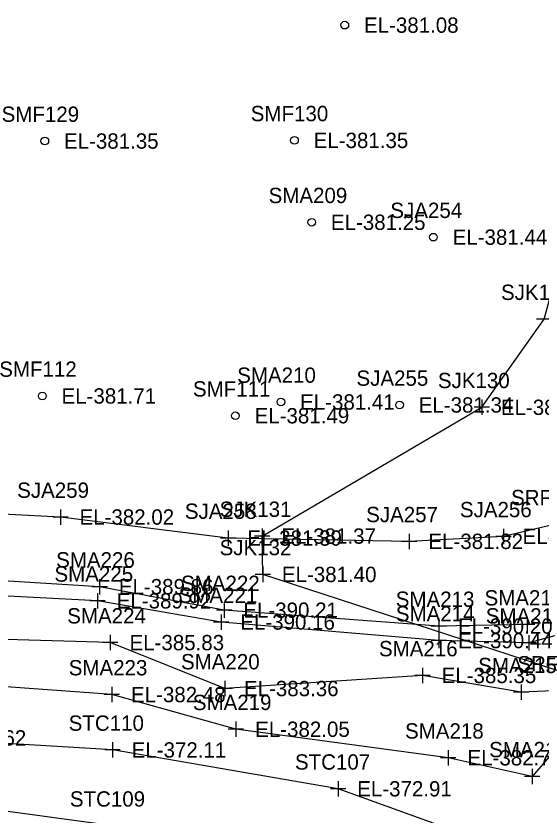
# Model space of a CAD drawing. Extents: x 1189978 to 1314812, y 571533 to 629339.
# Drawn here: x 1217385.9 to 1217522.9, y 621752.1 to 621960.6 of the extents above; entities that cross this region are included whole.
import ezdxf

# ---------------------------------------------------------------- set-up
doc = ezdxf.new("R2010")
doc.units = 0
for name, color, linetype in [('SURVEY - DRAINAGE - Bridge Hydraulic Data - Points - Elevations', 7, 'Continuous'), ('SURVEY - DRAINAGE - Bridge Hydraulic Data - Points - Numbers', 7, 'Continuous'), ('SURVEY - DRAINAGE - Bridge Hydraulic Data with Text', 7, 'Continuous'), ('SURVEY - DRAINAGE - Natural Features', 7, 'Continuous'), ('SURVEY - DRAINAGE - Natural Features - Points - Numbers', 7, 'Continuous'), ('SURVEY - DTM - Breaklines', 7, 'Continuous'), ('SURVEY - DTM - Breaklines - Points - Elevations', 7, 'Continuous'), ('SURVEY - DTM - Breaklines - Points - Locators', 7, 'Continuous'), ('SURVEY - DTM - Breaklines - Points - Numbers', 7, 'Continuous'), ('SURVEY - DTM - Spot Points - Elevations', 7, 'Continuous'), ('SURVEY - DTM - Spot Points - Locators', 7, 'Continuous'), ('SURVEY - DTM - Spot Points - Point Numbers', 7, 'Continuous'), ('SURVEY - VEGETATION - Features - Points - Elevations', 7, 'Continuous'), ('SURVEY - VEGETATION - Features - Points - Locators', 7, 'Continuous'), ('SURVEY - VEGETATION - Features - Points - Numbers', 7, 'Continuous'), ('SURVEY - VEGETATION - Features with Text', 7, 'Continuous')]:
    doc.layers.add(name, color=color, linetype=linetype)

msp = doc.modelspace()

# ---------------------------------------------------------------- linework, layer by layer
at = {"layer": 'SURVEY - DRAINAGE - Bridge Hydraulic Data with Text'}
for p, q in [((1217410.9, 621785.5), (1217410.9, 621781.5)), ((1217412.9, 621783.5), (1217408.9, 621783.5)), ((1217443.29, 621776.44), (1217443.29, 621772.44)), ((1217445.29, 621774.44), (1217441.29, 621774.44)), ((1217411.07, 621771.04), (1217411.07, 621767.04)), ((1217413.07, 621769.04), (1217409.07, 621769.04)), ((1217498.68, 621769), (1217498.68, 621765)), ((1217500.68, 621767), (1217496.68, 621767)), ((1217520.57, 621764.14), (1217520.57, 621760.14)), ((1217522.57, 621762.14), (1217518.57, 621762.14)), ((1217469.91, 621760.9), (1217469.91, 621756.9)), ((1217471.91, 621758.9), (1217467.91, 621758.9))]:
    msp.add_line(p, q, dxfattribs=at)
for points in [[(1217517.89, 621741.61), (1217469.91, 621758.9), (1217411.07, 621769.04), (1217358.89, 621772.19), (1217311.12, 621779.99), (1217259.84, 621789.4), (1217219.68, 621791.7), (1217168.44, 621804.62), (1217102.61, 621815.67), (1217052.63, 621809.41), (1217001.8, 621792.08), (1216983.34, 621768.8), (1216930.91, 621758.26)], [(1217410.9, 621783.5), (1217348.6, 621788.05), (1217293.38, 621789.05)], [(1217537.02, 621781.08), (1217520.57, 621762.14), (1217498.68, 621767), (1217443.29, 621774.44), (1217410.9, 621783.5)]]:
    msp.add_lwpolyline(points, dxfattribs=at)
at = {"layer": 'SURVEY - DRAINAGE - Natural Features'}
msp.add_lwpolyline([(1217597.92, 621711.33), (1217564.54, 621718.36), (1217512.62, 621725.38), (1217463.25, 621735.87), (1217411.22, 621749.25), (1217354.3, 621757.02), (1217307.69, 621764.42), (1217256.95, 621775.42), (1217216.84, 621778.16), (1217165.85, 621785.07), (1217102.13, 621795.43), (1217054.86, 621791.1), (1217006.99, 621774.19), (1216986.41, 621760.64), (1216952.38, 621744.49)], dxfattribs=at)
at = {"layer": 'SURVEY - DTM - Breaklines'}
for points in [[(1217685.05, 622529.18), (1217678.55, 622499.44), (1217670.66, 622464.16), (1217662, 622418.29), (1217653.65, 622375.31), (1217647.46, 622326.5), (1217637.7, 622278.06), (1217624.97, 622233.51), (1217617.77, 622187.81), (1217609.29, 622147.05), (1217599.66, 622101.36), (1217592.56, 622056.45), (1217583.44, 622007.19), (1217575.28, 621964.22), (1217564.77, 621919.14), (1217554.54, 621865.01), (1217546.46, 621821.67), (1217537.02, 621781.08), (1217528.09, 621784.53), (1217517.71, 621784.08)], [(1217526.29, 621827.9), (1217513.05, 621824.77), (1217488.49, 621823.48), (1217441.24, 621824.34), (1217397.47, 621829.83), (1217345.53, 621832.46), (1217295.63, 621831.2), (1217245.72, 621829.59), (1217196.06, 621848.65), (1217142.73, 621858.18), (1217088.87, 621861), (1217031.95, 621852.21), (1216981.96, 621833.21)], [(1217519.22, 621801.74), (1217496.21, 621801.38), (1217440.2, 621805.52), (1217407.73, 621811.65), (1217355.92, 621814.85), (1217296.27, 621811.58)], [(1217534.84, 621801.11), (1217519.7, 621797.03), (1217496.23, 621797.58), (1217439.41, 621802.43), (1217407.18, 621807.95), (1217355.45, 621810.65), (1217295.81, 621806.41)], [(1217517.71, 621784.08), (1217491.94, 621788.48), (1217440.37, 621785.07), (1217410.51, 621797.05), (1217352.9, 621798.74)]]:
    msp.add_lwpolyline(points, dxfattribs=at)
at = {"layer": 'SURVEY - DTM - Breaklines - Points - Locators'}
for p, q in [((1217397.47, 621831.83), (1217397.47, 621827.83)), ((1217399.47, 621829.83), (1217395.47, 621829.83)), ((1217441.24, 621826.34), (1217441.24, 621822.34)), ((1217513.05, 621826.77), (1217513.05, 621822.77)), ((1217443.24, 621824.34), (1217439.24, 621824.34)), ((1217488.49, 621825.48), (1217488.49, 621821.48)), ((1217515.05, 621824.77), (1217511.05, 621824.77)), ((1217490.49, 621823.48), (1217486.49, 621823.48)), ((1217407.73, 621813.65), (1217407.73, 621809.65)), ((1217409.73, 621811.65), (1217405.73, 621811.65)), ((1217407.18, 621809.95), (1217407.18, 621805.95)), ((1217409.18, 621807.95), (1217405.18, 621807.95)), ((1217440.2, 621807.52), (1217440.2, 621803.52)), ((1217442.2, 621805.52), (1217438.2, 621805.52)), ((1217439.41, 621804.43), (1217439.41, 621800.43)), ((1217496.21, 621803.38), (1217496.21, 621799.38)), ((1217519.22, 621803.74), (1217519.22, 621799.74)), ((1217441.41, 621802.43), (1217437.41, 621802.43)), ((1217498.21, 621801.38), (1217494.21, 621801.38)), ((1217521.22, 621801.74), (1217517.22, 621801.74)), ((1217410.51, 621799.05), (1217410.51, 621795.05)), ((1217496.23, 621799.58), (1217496.23, 621795.58)), ((1217519.7, 621799.03), (1217519.7, 621795.03)), ((1217412.51, 621797.05), (1217408.51, 621797.05)), ((1217498.23, 621797.58), (1217494.23, 621797.58)), ((1217521.7, 621797.03), (1217517.7, 621797.03)), ((1217491.94, 621790.48), (1217491.94, 621786.48)), ((1217493.94, 621788.48), (1217489.94, 621788.48)), ((1217440.37, 621787.07), (1217440.37, 621783.07)), ((1217442.37, 621785.07), (1217438.37, 621785.07)), ((1217519.71, 621784.08), (1217515.71, 621784.08)), ((1217517.71, 621786.08), (1217517.71, 621782.08))]:
    msp.add_line(p, q, dxfattribs=at)
at = {"layer": 'SURVEY - DTM - Spot Points - Locators'}
for centre in [(1217471.68, 621958.19), (1217393.42, 621927.95), (1217458.55, 621928.12), (1217463.05, 621906.75), (1217494.8, 621902.86), (1217392.77, 621861.42), (1217455.02, 621859.85), (1217485.96, 621859.07), (1217443.14, 621856.26)]:
    msp.add_circle(centre, 1, dxfattribs=at)
at = {"layer": 'SURVEY - VEGETATION - Features - Points - Locators'}
for p, q in [((1217525.69, 621881.47), (1217521.69, 621881.47)), ((1217507.38, 621860.46), (1217507.38, 621856.46)), ((1217509.38, 621858.46), (1217505.38, 621858.46)), ((1217450.11, 621826.86), (1217450.11, 621822.86)), ((1217452.11, 621824.86), (1217448.11, 621824.86)), ((1217450.26, 621816.85), (1217450.26, 621812.85)), ((1217450.26, 621816.85), (1217450.26, 621812.85)), ((1217452.26, 621814.85), (1217448.26, 621814.85)), ((1217452.26, 621814.85), (1217448.26, 621814.85))]:
    msp.add_line(p, q, dxfattribs=at)
at = {"layer": 'SURVEY - VEGETATION - Features with Text'}
msp.add_lwpolyline([(1217575.08, 621774.11), (1217450.26, 621814.85), (1217450.11, 621824.86), (1217507.38, 621858.46), (1217523.69, 621881.47), (1217539.67, 621940.19), (1217555.11, 622005.06), (1217569.39, 622072.91), (1217588.39, 622140.3), (1217598.23, 622184.22), (1217608.56, 622234.27), (1217619.43, 622285.83), (1217630.65, 622335.58), (1217641.81, 622391.46), (1217652.67, 622449.04), (1217659.71, 622500.99), (1217665.15, 622519.94)], dxfattribs=at)

# ---------------------------------------------------------------- texts
at = {"layer": 'SURVEY - DRAINAGE - Bridge Hydraulic Data - Points - Elevations'}
for s, p in [('EL-382.48', (1217415.9, 621781.5)), ('EL-382.05', (1217448.29, 621772.44)), ('EL-372.62', (1217363.89, 621770.19)), ('EL-372.11', (1217416.07, 621767.04)), ('EL-382.74', (1217503.68, 621765)), ('EL-372.91', (1217474.91, 621756.9))]:
    msp.add_text(s, height=4, dxfattribs=at).set_placement(p)
at = {"layer": 'SURVEY - DRAINAGE - Bridge Hydraulic Data - Points - Numbers'}
for s, p in [('SMA223', (1217399.66, 621788.5)), ('SMA219', (1217432.03, 621779.44)), ('STC110', (1217399.65, 621774.04)), ('SMA218', (1217487.39, 621772)), ('SMA217', (1217509.33, 621767.14)), ('STC107', (1217458.67, 621763.9))]:
    msp.add_text(s, height=4, dxfattribs=at).set_placement(p)
at = {"layer": 'SURVEY - DRAINAGE - Natural Features - Points - Numbers'}
msp.add_text('STC109', height=4, dxfattribs=at).set_placement((1217399.96, 621754.25))
at = {"layer": 'SURVEY - DTM - Breaklines - Points - Elevations'}
for s, p in [('EL-382.02', (1217402.47, 621827.83)), ('EL-381.39', (1217446.24, 621822.34)), ('EL-382.25', (1217518.05, 621822.77)), ('EL-381.82', (1217493.49, 621821.48)), ('EL-389.86', (1217412.73, 621809.65)), ('EL-389.92', (1217412.18, 621805.95)), ('EL-390.21', (1217445.2, 621803.52)), ('EL-390.16', (1217444.41, 621800.43)), ('EL-390.20', (1217501.21, 621799.38)), ('EL-385.83', (1217415.51, 621795.05)), ('EL-390.44', (1217501.23, 621795.58)), ('EL-385.35', (1217496.94, 621786.48)), ('EL-383.36', (1217445.37, 621783.07))]:
    msp.add_text(s, height=4, dxfattribs=at).set_placement(p)
at = {"layer": 'SURVEY - DTM - Breaklines - Points - Numbers'}
for s, p in [('SJA259', (1217386.21, 621834.83)), ('SRF255', (1217515.05, 621832.9)), ('SJA258', (1217429.95, 621829.34)), ('SJA257', (1217477.25, 621828.48)), ('SJA256', (1217501.7, 621829.77)), ('SMA226', (1217396.38, 621816.65)), ('SMA225', (1217395.94, 621812.95)), ('SMA222', (1217428.96, 621810.52)), ('SMA221', (1217428.33, 621807.43)), ('SMA213', (1217484.97, 621806.38)), ('SMA211', (1217508.13, 621806.74)), ('SMA224', (1217399.27, 621802.05)), ('SMA214', (1217484.99, 621802.58)), ('SMA212', (1217508.46, 621802.03)), ('SMA216', (1217480.59, 621793.48)), ('SMA220', (1217428.95, 621790.07)), ('SMA215', (1217506.47, 621789.08)), ('SRF260', (1217516.68, 621789.53))]:
    msp.add_text(s, height=4, dxfattribs=at).set_placement(p)
at = {"layer": 'SURVEY - DTM - Spot Points - Elevations'}
for s, p in [('EL-381.08', (1217476.68, 621956.19)), ('EL-381.35', (1217398.42, 621925.95)), ('EL-381.35', (1217463.55, 621926.12)), ('EL-381.25', (1217468.05, 621904.75)), ('EL-381.44', (1217499.8, 621900.86)), ('EL-381.71', (1217397.77, 621859.42)), ('EL-381.41', (1217460.02, 621857.85)), ('EL-381.34', (1217490.96, 621857.07)), ('EL-381.49', (1217448.14, 621854.26))]:
    msp.add_text(s, height=4, dxfattribs=at).set_placement(p)
at = {"layer": 'SURVEY - DTM - Spot Points - Point Numbers'}
for s, p in [('SMF129', (1217382.16, 621932.95)), ('SMF130', (1217447.14, 621933.12)), ('SMA209', (1217451.8, 621911.75)), ('SJA254', (1217483.56, 621907.86)), ('SMF112', (1217381.53, 621866.42)), ('SMA210', (1217443.61, 621864.85)), ('SJA255', (1217474.72, 621864.07)), ('SMF111', (1217432.06, 621861.26))]:
    msp.add_text(s, height=4, dxfattribs=at).set_placement(p)
at = {"layer": 'SURVEY - VEGETATION - Features - Points - Elevations'}
for s, p in [('EL-381.34', (1217512.38, 621856.46)), ('EL-381.37', (1217455.11, 621822.86)), ('EL-381.40', (1217455.26, 621812.85)), ('EL-381.40', (1217455.26, 621812.85))]:
    msp.add_text(s, height=4, dxfattribs=at).set_placement(p)
at = {"layer": 'SURVEY - VEGETATION - Features - Points - Numbers'}
for s, p in [('SJK129', (1217512.43, 621886.47)), ('SJK130', (1217495.96, 621863.46)), ('SJK131', (1217439.03, 621829.86)), ('SJK132', (1217439.02, 621819.85)), ('SJK132', (1217439.02, 621819.85))]:
    msp.add_text(s, height=4, dxfattribs=at).set_placement(p)

doc.saveas('drawing.dxf')
